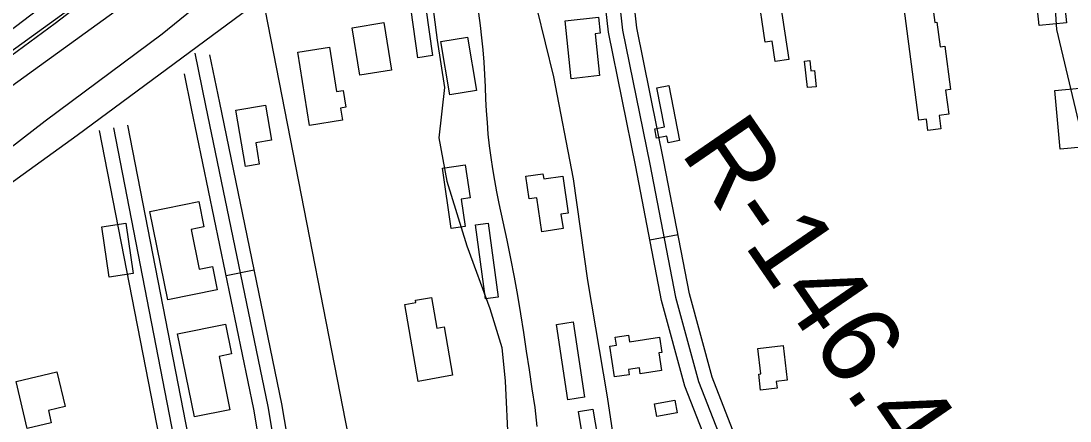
# Model space of a CAD drawing. Extents: x 3477039 to 3515015, y 546746 to 572297.
# Drawn here: x 3488491 to 3489585, y 559664 to 560081 of the extents above; entities that cross this region are included whole.
import ezdxf

# ---------------------------------------------------------------- set-up
doc = ezdxf.new("R2010")
doc.units = 0
for name, color, linetype in [('V-BLDG-OTLN', 7, 'Continuous'), ('V-FLOD-BASE', 7, 'Continuous'), ('V-LEVE-TOET', 7, 'Continuous'), ('V-RIVR-RANG-IDEN', 7, 'Continuous'), ('V-ROAD-CNTR', 7, 'Continuous'), ('V-SURV-LINE', 7, 'Continuous')]:
    doc.layers.add(name, color=color, linetype=linetype)

msp = doc.modelspace()

# ---------------------------------------------------------------- linework, layer by layer
at = {"layer": 'V-BLDG-OTLN'}
for points in [[(3489577.2, 560122.5), (3489581.9, 560079.6), (3489553.3, 560076.5), (3489548.7, 560119.4)], [(3489280.8, 560117.1), (3489292.1, 560041.2), (3489277.8, 560039.1), (3489274.6, 560060.2), (3489267.6, 560059.1), (3489259.5, 560113.9)], [(3489427.8, 559978), (3489411.8, 560100), (3489441.2, 560103.9), (3489444.3, 560079.8), (3489446.6, 560080.1), (3489449.9, 560054.5), (3489454.9, 560055.2), (3489460.9, 560009.7), (3489455.7, 560009), (3489458.9, 559984.1), (3489449, 559982.8), (3489450.8, 559968.8), (3489437.3, 559967.1), (3489435.7, 559979)], [(3488913.6, 560094.7), (3488920.5, 560045.2), (3488905.2, 560043), (3488898.3, 560092.5)], [(3488869.6, 560079.7), (3488877.5, 560030.2), (3488844.5, 560024.9), (3488836.6, 560074.4)], [(3489090.1, 560068.1), (3489094.8, 560024.3), (3489065.2, 560021.1), (3489058.8, 560081.7), (3489093.6, 560085.4), (3489095.3, 560068.7)], [(3488957, 560064.5), (3488966.2, 560008.9), (3488938.4, 560004.3), (3488929.1, 560059.9)], [(3488812.9, 560054), (3488820.3, 560007.8), (3488827.1, 560008.9), (3488830, 559991.3), (3488824.6, 559990.5), (3488826.6, 559978), (3488792.1, 559972.4), (3488779.8, 560048.7)], [(3489311.5, 560011.8), (3489308.6, 560039.6), (3489313.9, 560040.2), (3489315, 560029.2), (3489318.8, 560029.6), (3489320.6, 560012.8)], [(3489167.1, 560014), (3489178.2, 559956.5), (3489166.2, 559954.2), (3489164.8, 559961.1), (3489154.2, 559959.1), (3489152.3, 559968.8), (3489162.5, 559970.8), (3489154.6, 560011.6)], [(3489595.7, 560011.3), (3489601.5, 559950), (3489575.3, 559947.5), (3489569.5, 560008.8)], [(3488746.3, 559993.6), (3488752.4, 559956.9), (3488736, 559954.1), (3488739.7, 559932), (3488725.2, 559929.6), (3488715.3, 559988.4)], [(3488940, 559864.8), (3488930.9, 559927.9), (3488954.6, 559931.3), (3488959.6, 559896.7), (3488950.3, 559895.4), (3488954.4, 559866.8)], [(3489056.4, 559919.4), (3489062, 559880.7), (3489054.4, 559879.6), (3489056.6, 559864.6), (3489034.3, 559861.4), (3489029.1, 559896.9), (3489021.2, 559895.8), (3489017.7, 559919.3), (3489035.6, 559921.9), (3489036.4, 559916.5)], [(3488668.5, 559863.8), (3488677, 559822.3), (3488690.9, 559825.1), (3488695.9, 559800.7), (3488644.3, 559790.2), (3488625.6, 559882.5), (3488676.7, 559892.9), (3488682, 559866.5)], [(3488600.4, 559870.2), (3488608.2, 559817.9), (3488583.1, 559814.1), (3488575.3, 559866.5)], [(3488978.6, 559870.4), (3488989, 559793.2), (3488975.8, 559791.4), (3488965.4, 559868.7)], [(3488905.6, 559705.2), (3488891.5, 559785.4), (3488903, 559787.4), (3488902.6, 559789.8), (3488919.5, 559792.8), (3488925.1, 559760.8), (3488932.5, 559762.1), (3488941.4, 559711.5)], [(3488672.3, 559668), (3488654.5, 559754.8), (3488704.5, 559765), (3488710.9, 559733.8), (3488697.7, 559731.1), (3488709.1, 559675.6)], [(3489067.3, 559767.3), (3489079, 559688.6), (3489061.6, 559686), (3489049.9, 559764.7)], [(3489110.3, 559709.8), (3489105.5, 559741.9), (3489112.4, 559742.9), (3489111.1, 559751.4), (3489124.9, 559753.4), (3489125.9, 559746.5), (3489157.1, 559751.2), (3489159.5, 559735.3), (3489156.6, 559734.8), (3489159.3, 559716.4), (3489137.1, 559713.1), (3489136.2, 559719.2), (3489125, 559717.6), (3489125.7, 559712.1)], [(3489286.2, 559742.6), (3489290.5, 559706.3), (3489279.1, 559705), (3489279.9, 559698), (3489262.6, 559695.9), (3489260.7, 559712.8), (3489262.8, 559713), (3489259.9, 559739.5)], [(3488497.6, 559656), (3488486, 559705.1), (3488528.6, 559715.2), (3488537.2, 559679.1), (3488519.7, 559674.9), (3488522.7, 559661.9)], [(3489173.1, 559685.6), (3489175.6, 559672.3), (3489154.4, 559668.4), (3489151.9, 559681.6)], [(3489087.8, 559676.2), (3489100.1, 559602.7), (3489084.9, 559600.2), (3489072.6, 559673.7)]]:
    msp.add_lwpolyline(points, close=True, dxfattribs=at)
at = {"layer": 'V-FLOD-BASE'}
msp.add_lwpolyline([(3488453.8, 560025.4), (3488526.7, 560079.2), (3488626.2, 560155.7), (3488753.7, 560246.4), (3488868.5, 560331.5), (3488976.8, 560409.8), (3489097.9, 560494.7), (3489213.7, 560579.9), (3489323.9, 560658.1), (3489459.4, 560755.6), (3489544, 560815.1), (3489566.2, 560831), (3489591.3, 560851.8), (3489647.2, 560910.2), (3489740.6, 561008.2), (3489803.9, 561075.3), (3489833.6, 561102.8), (3489868.6, 561133.6), (3489886.8, 561146.6), (3489940.4, 561176.2), (3490057.8, 561237.3), (3490198.3, 561310.3), (3490291.1, 561359.5), (3490350.6, 561389)], dxfattribs=at)
at = {"layer": 'V-LEVE-TOET'}
for points in [[(3488403.4, 559889.7), (3488516.3, 559977.2), (3488638.4, 560068.1), (3488739.5, 560150.3), (3488860.4, 560239.3), (3488952.5, 560306.6), (3489085, 560399.2), (3489202.2, 560482.8), (3489317.8, 560561.9), (3489470, 560671.4), (3489592.1, 560761.8), (3489634.5, 560797.4), (3489701.2, 560859.1), (3489771.3, 560929.5), (3489851.9, 561014.5), (3489916.6, 561077.2), (3489933.4, 561089.7), (3489978.1, 561111.1), (3490050.7, 561145.4), (3490064, 561154.5), (3490069.9, 561158.6), (3490118.7, 561192.9), (3490227.3, 561254.6), (3490352.1, 561323.4)], [(3489615.6, 560917.9), (3489565.1, 560864.8), (3489524.2, 560829.6), (3489453.3, 560782.2), (3489353, 560717), (3489236.2, 560627.5), (3489124.4, 560547.3), (3489019.6, 560473.9), (3488901.3, 560386), (3488777.3, 560296.6), (3488642.8, 560200.1), (3488546.7, 560122.2), (3488456, 560052.9)]]:
    msp.add_lwpolyline(points, dxfattribs=at)
at = {"layer": 'V-ROAD-CNTR'}
for p, q in [((3489147.1, 559852.8), (3489176.6, 559858.5)), ((3488705, 559815.6), (3488734.4, 559821.7))]:
    msp.add_line(p, q, dxfattribs=at)
for points in [[(3489503.8, 560654.9), (3489213.9, 560445.6), (3488846.6, 560181.8), (3488549.7, 559962), (3488303.8, 559784.4), (3488052.8, 559612.8), (3487878.9, 559494.3)], [(3489503.8, 560654.9), (3489213.9, 560445.6), (3488846.6, 560181.8), (3488549.7, 559962), (3488303.8, 559784.4), (3488052.8, 559612.8), (3487878.9, 559494.3)], [(3489488.6, 560625.4), (3489510, 560587.9), (3489521.7, 560546.4), (3489526.2, 560502), (3489532.4, 560441.1), (3489541.7, 560383.3), (3489548.8, 560330.5), (3489562.8, 560205.6), (3489571.4, 560072.4), (3489600.8, 559947.9), (3489609.3, 559845.2), (3489630.3, 559711.8), (3489635.1, 559666.6)], [(3488978.2, 560265.7), (3488997.7, 560215.6), (3489020.6, 560129.9), (3489046.6, 560023.2), (3489067.3, 559916.5), (3489082.2, 559810.4), (3489102.7, 559689.1), (3489125.3, 559538), (3489140.1, 559429.9)], [(3489101.2, 560268.9), (3489108.9, 560160), (3489118.7, 560071.9), (3489147.1, 559931.9), (3489173.9, 559793.1), (3489197.9, 559704.9), (3489245.8, 559582.3), (3489263.2, 559463.6), (3489298.2, 559201.5), (3489315.7, 559162.7), (3489367.1, 558851.3), (3489399.3, 558654.4)], [(3489574, 557645.5), (3489561.4, 557758.1), (3489509.7, 558063.2), (3489470.8, 558321.2), (3489414.1, 558656.9), (3489381.9, 558853.7), (3489330.1, 559167.1), (3489312.8, 559205.6), (3489278.1, 559465.6), (3489260.3, 559586.2), (3489212.2, 559709.6), (3489188.6, 559796.5), (3489161.8, 559934.8), (3489133.6, 560074.2), (3489123.9, 560161.4), (3489116.1, 560270)], [(3489543.2, 557650.8), (3489531.7, 557753.9), (3489480.1, 558058.4), (3489441.1, 558316.5), (3489384.5, 558652), (3489352.3, 558848.9), (3489301.2, 559158.3), (3489283.6, 559197.3), (3489248.4, 559461.5), (3489231.2, 559578.4), (3489183.6, 559700.2), (3489159.3, 559789.7), (3489132.4, 559929), (3489103.9, 560069.6), (3489094, 560158.6), (3489086.6, 560262.6)], [(3488891.1, 560188.2), (3488907.7, 560148.1), (3488919.4, 560107.2), (3488925.3, 560061.3), (3488932.8, 560012), (3488926.9, 559959.3), (3488935.2, 559914.2), (3488956.1, 559846.5), (3488980.3, 559781.4), (3488992.8, 559740.5), (3488996.1, 559705.4), (3488999.4, 559639.4), (3488996.1, 559552.5), (3488991.1, 559479.8), (3488991.9, 559411.2)], [(3488746, 560092), (3488852.7, 559544.8)], [(3488968.4, 560089.4), (3488970.1, 560076.7), (3488971.6, 560063.9), (3488972.8, 560051.2), (3488973.9, 560038.4), (3488974.8, 560025.6), (3488975.4, 560012.7), (3488975.8, 559999.9), (3488976.4, 559987.7), (3488977.3, 559975.5), (3488978.3, 559963.3), (3488979.7, 559951.2), (3488981.2, 559939), (3488983, 559927), (3488985, 559914.9), (3488987.2, 559902.9), (3488989.6, 559890.9), (3488993.9, 559871.8), (3488998, 559852.6), (3489001.9, 559833.4), (3489005.6, 559814.1), (3489009, 559794.9), (3489012.3, 559775.5), (3489015.3, 559756.2), (3489018.1, 559736.8), (3489021.3, 559717.2), (3489024.2, 559697.5), (3489027, 559677.9), (3489029.4, 559658.2)], [(3488672.6, 560047.7), (3488683.7, 559993.1), (3488748.6, 559678.8), (3488785.3, 559462.6), (3488838.8, 559201.8), (3488895.6, 558902.6), (3488972.5, 558519.6), (3489008.8, 558317.8), (3489058.1, 558050.9)], [(3489072.9, 558053.6), (3489023.5, 558320.5), (3488987.2, 558522.4), (3488910.3, 558905.4), (3488853.5, 559204.7), (3488800.1, 559465.4), (3488763.4, 559681.6), (3488698.4, 559996.1), (3488688.2, 560046)], [(3489043.4, 558048.2), (3488994, 558315.1), (3488957.7, 558516.8), (3488880.8, 558899.7), (3488824.1, 559198.9), (3488770.6, 559459.9), (3488733.9, 559676), (3488669, 559990), (3488661.6, 560026.3)], [(3488587.5, 559969.8), (3488666.7, 559562.9), (3488705, 559463.5)], [(3488602.2, 559972.6), (3488681.1, 559567.1), (3488719, 559468.9)], [(3488572.8, 559966.9), (3488652.2, 559558.8), (3488691, 559458.1)]]:
    msp.add_lwpolyline(points, dxfattribs=at)
at = {"layer": 'V-SURV-LINE'}
for points in [[(3488067.7, 559751.2), (3489560.7, 560830.9)], [(3488067.7, 559751.2), (3489560.7, 560830.9)], [(3489578.3, 560806.6), (3488085.3, 559726.9)], [(3489578.3, 560806.6), (3488085.3, 559726.9)]]:
    msp.add_lwpolyline(points, dxfattribs=at)

# ---------------------------------------------------------------- texts
at = {"layer": 'V-RIVR-RANG-IDEN'}
msp.add_text('R-146.4', height=83, rotation=304.5134, dxfattribs=at).set_placement((3489178.2, 559944.5))

doc.saveas('drawing.dxf')
